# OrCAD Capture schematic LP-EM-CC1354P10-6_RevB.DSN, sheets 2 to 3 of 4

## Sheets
2 2_Peripherals: size A3
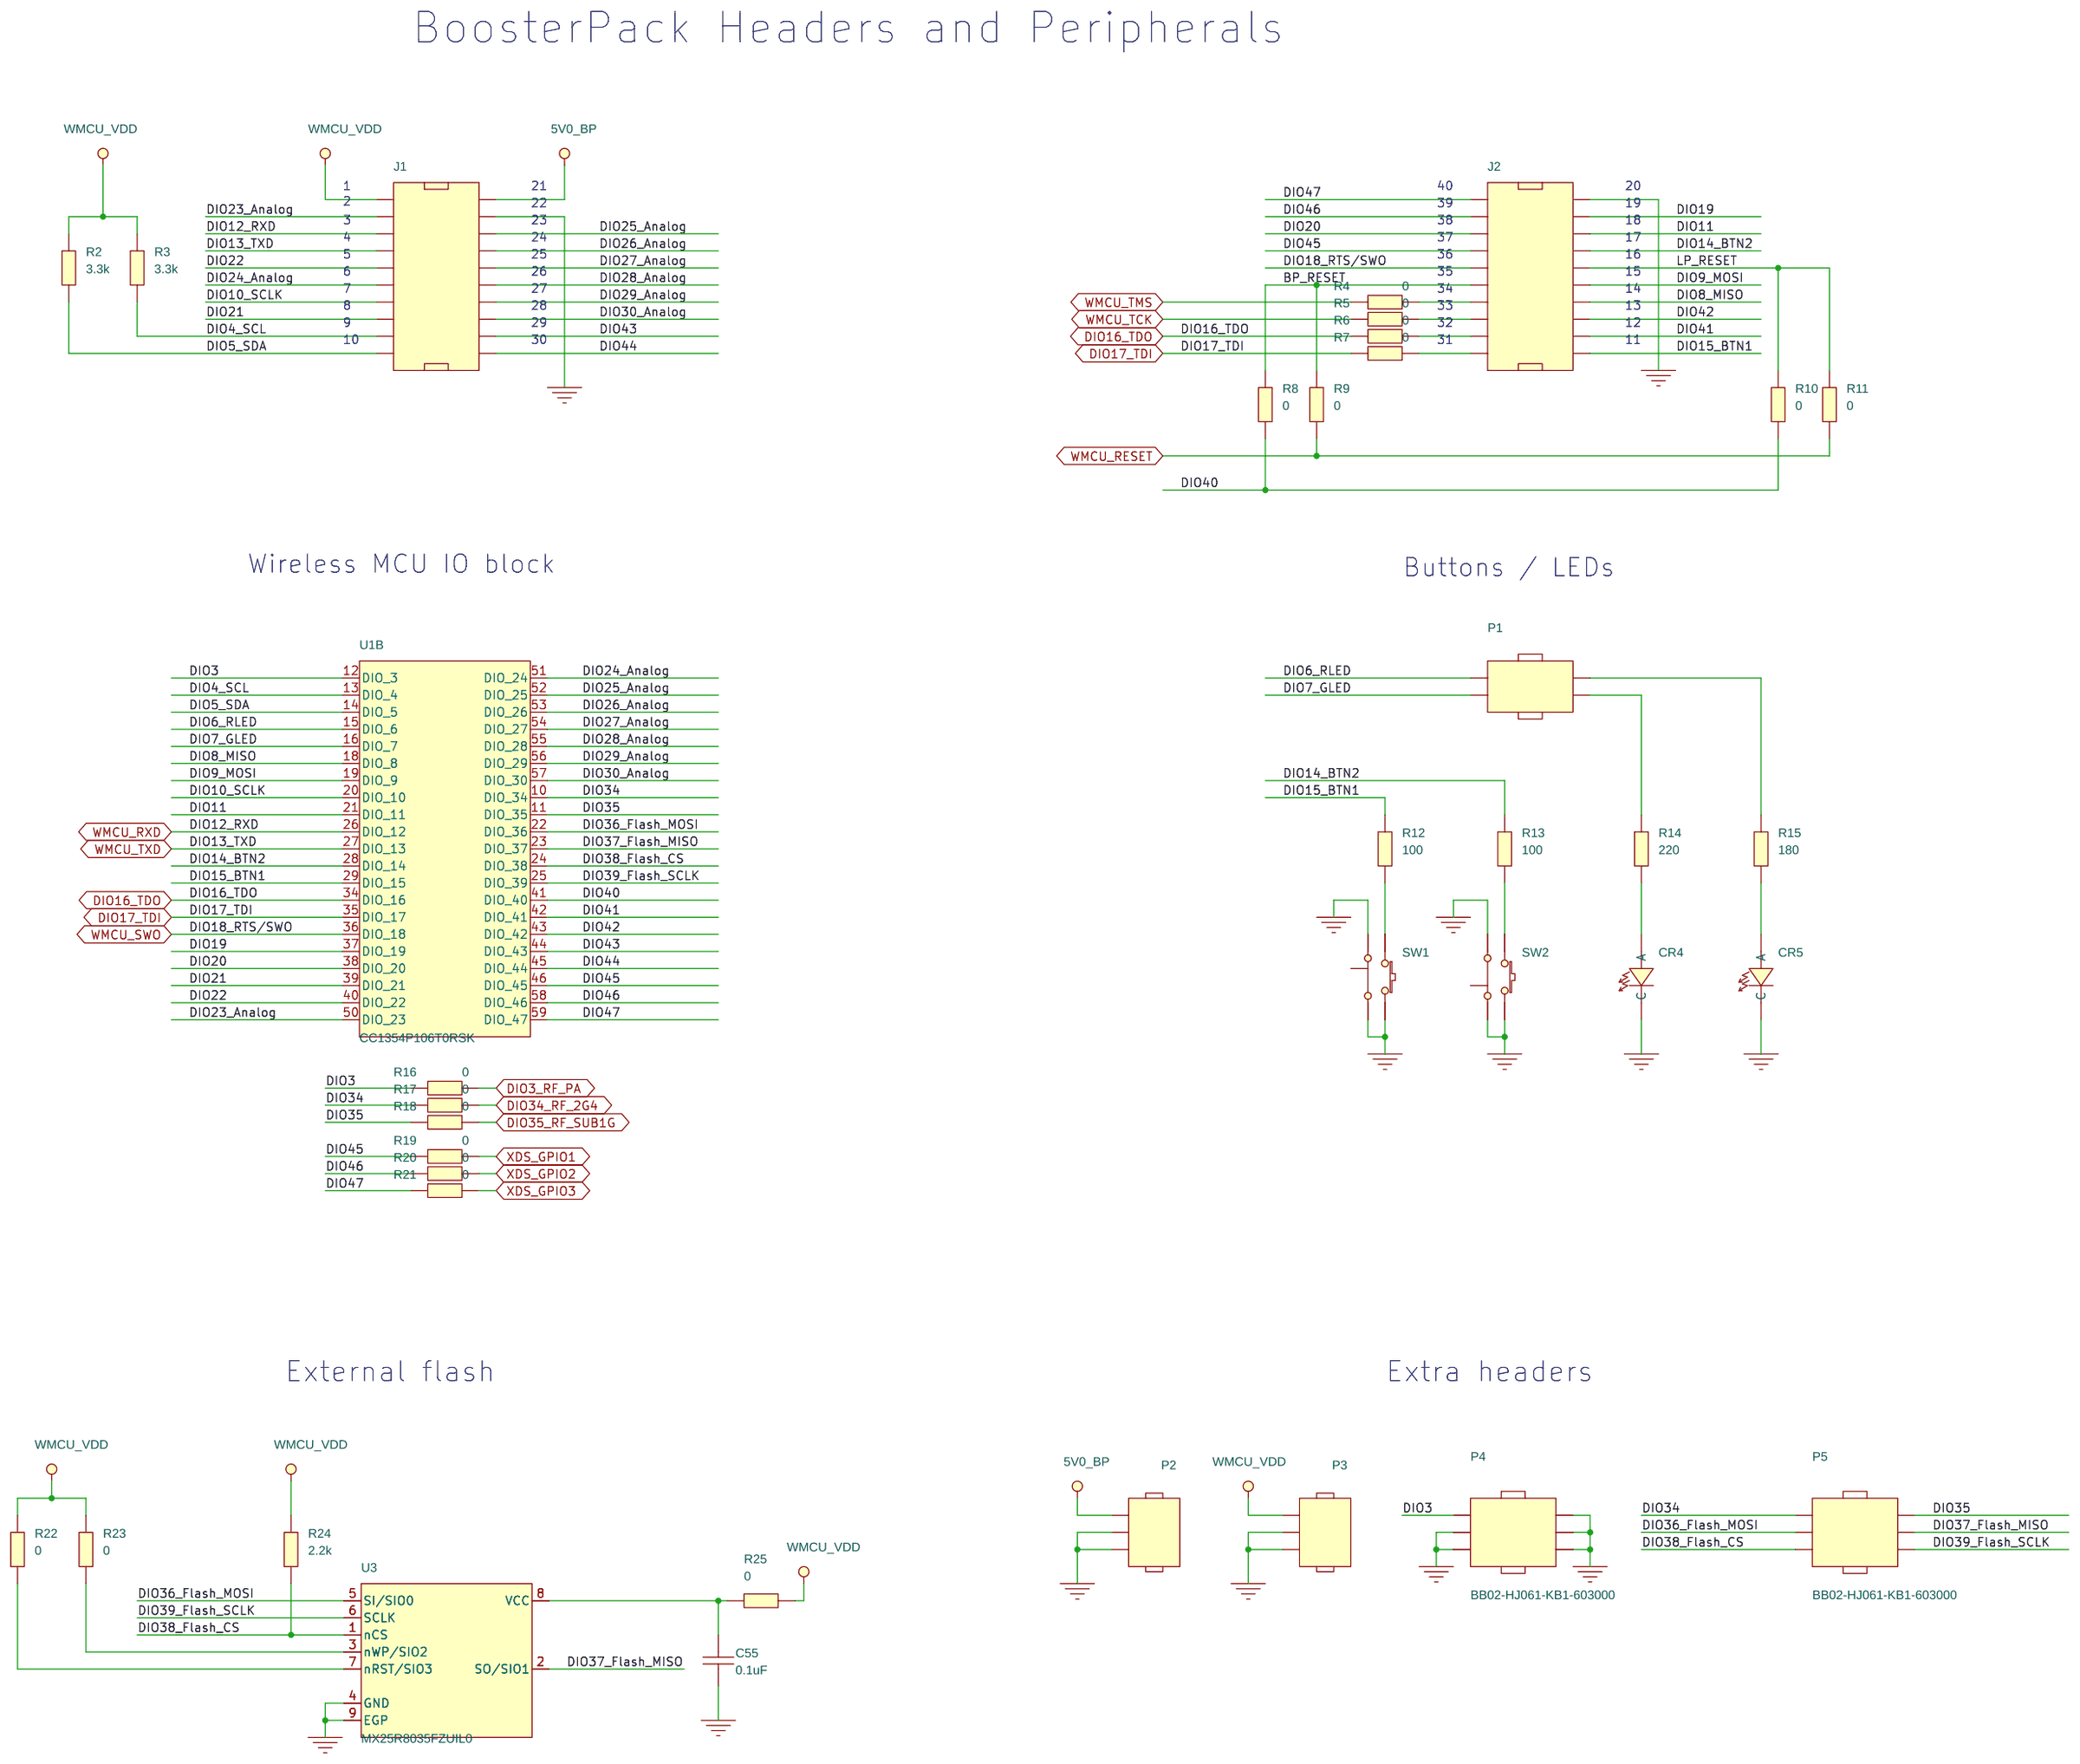
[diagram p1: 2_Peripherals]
3 3_Debugger Interface: size A3
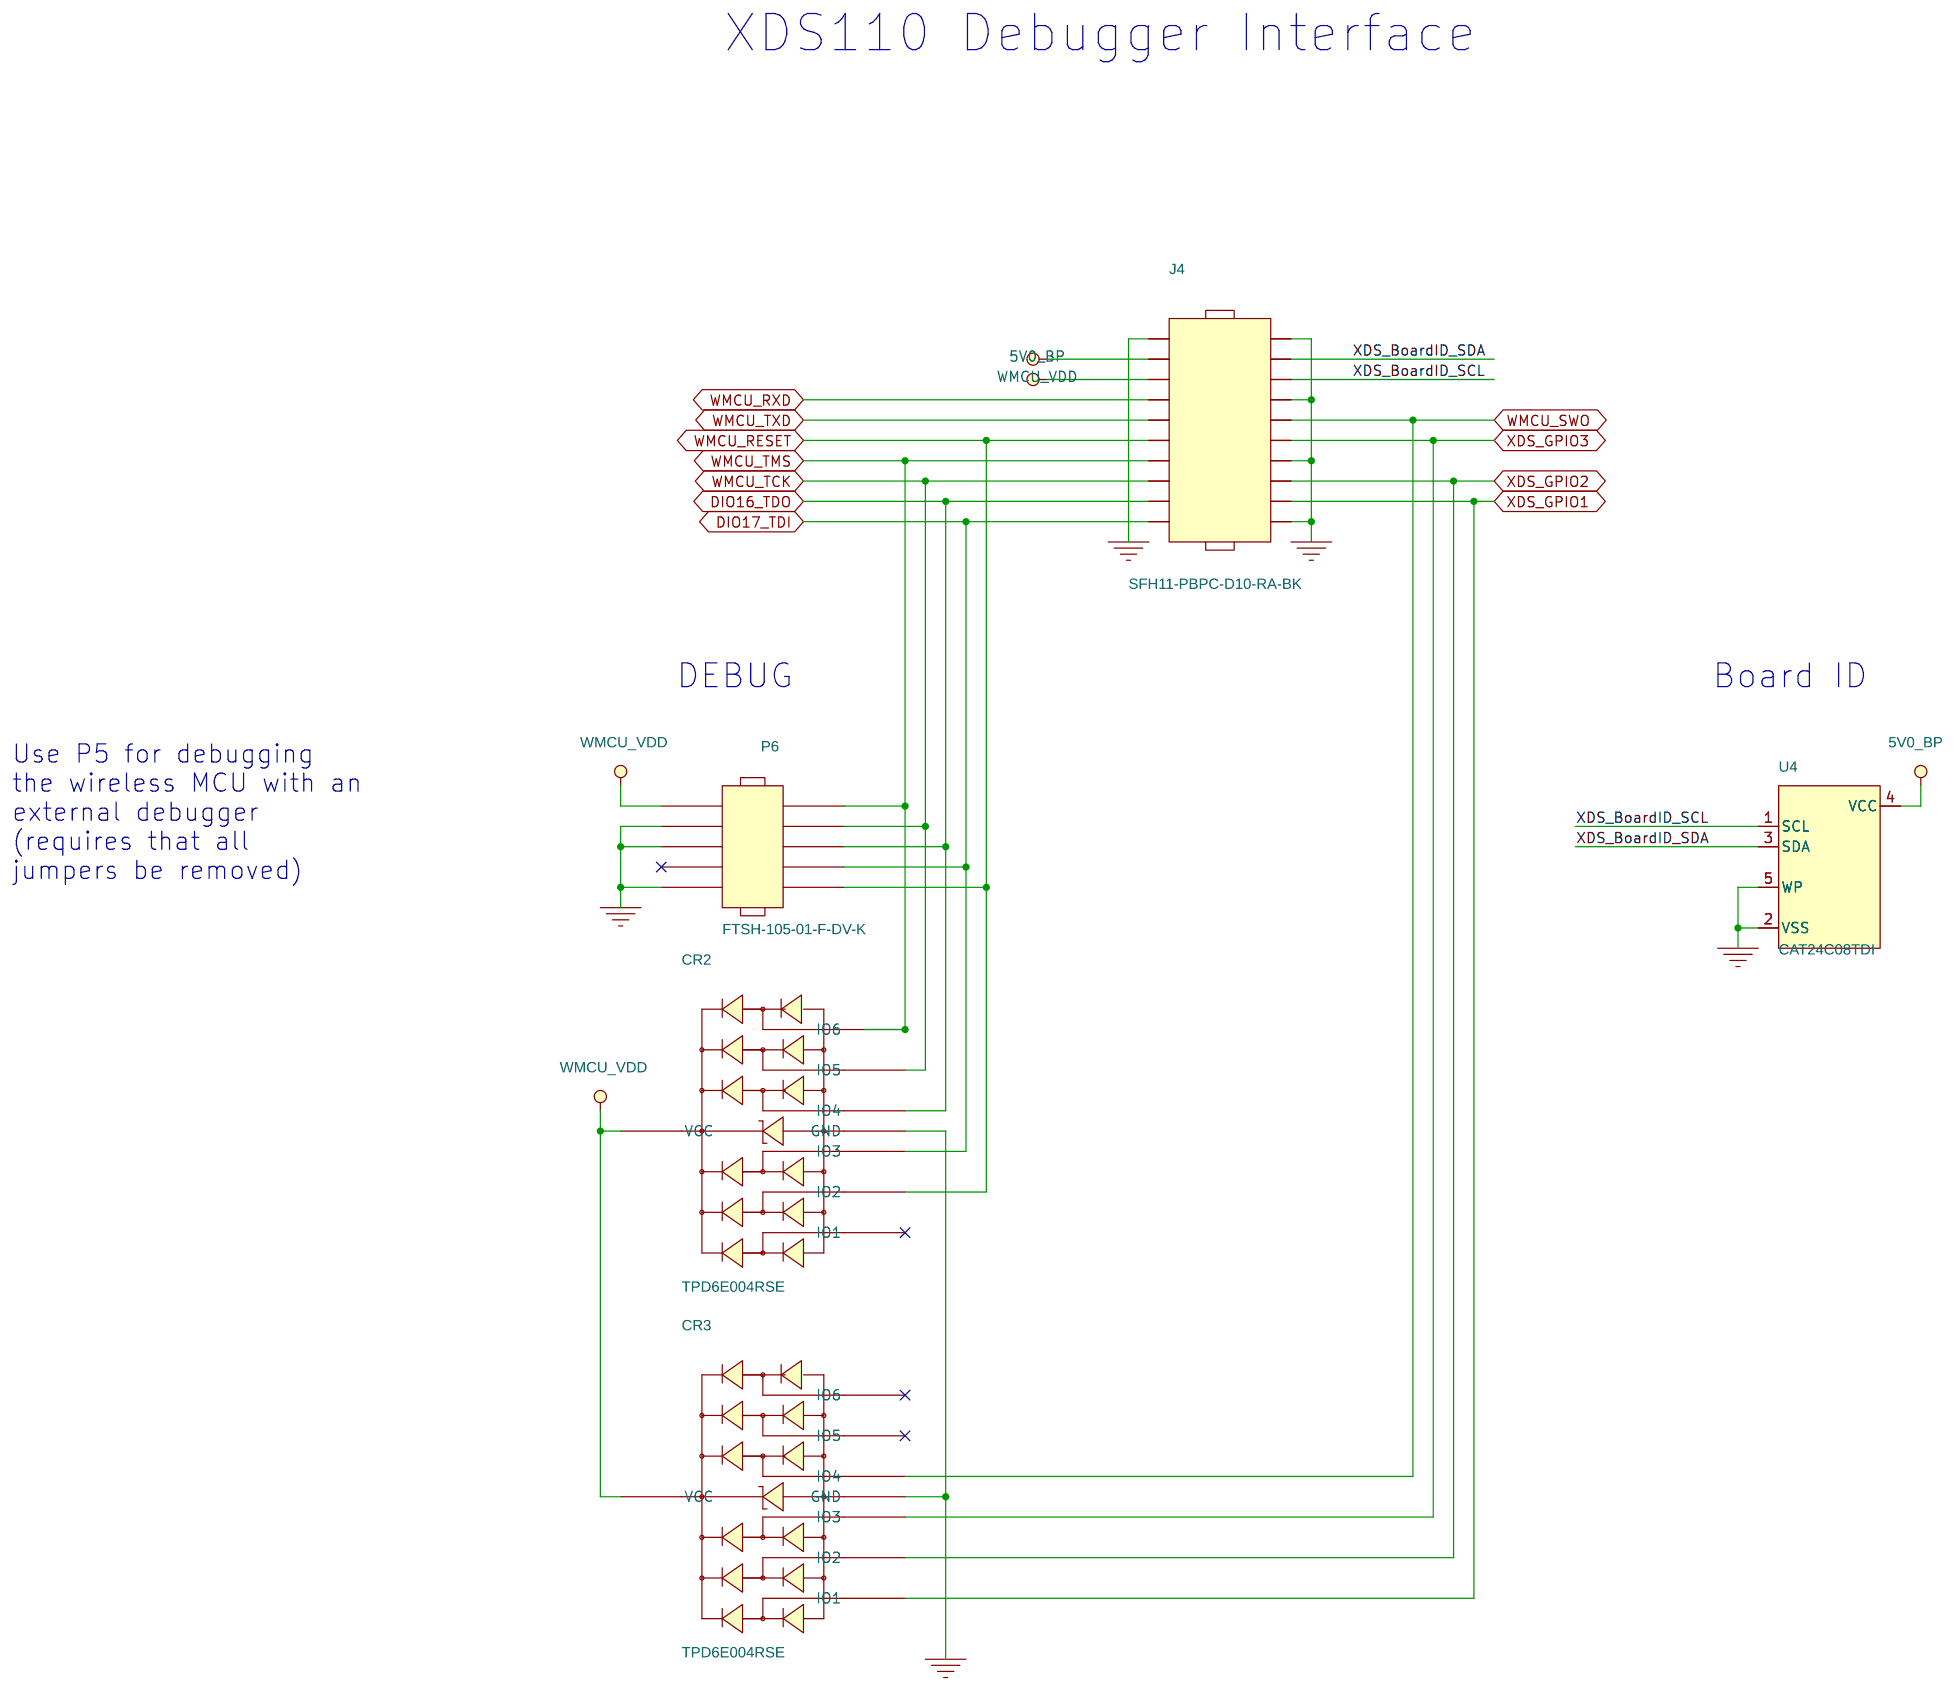
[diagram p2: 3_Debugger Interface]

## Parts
sheet 1_RF
U1  CC1354P106T0RSK  [QFNFC40P800X800X100-65A2N]  (sections A,B)
sheet 2_Peripherals
C55  0.1uF  [CAPC0603X35B2N]
CR4  LPL296-J2L2-25  [LEDC1707X65N]
CR5  LS L296-P2Q2-1  [LEDC1708X67N]
J1  SSQ-110-23-L-D  [SAMTEC_SSQ11023LD_A2B]
J2  SSQ-110-23-L-D  [SAMTEC_SSQ11023LD_A2B]
P1  BB02-HJ041-KB1-603000  [GRADCONN_BB02HJ041KB1603000_A2B]
P2  BB02-HC031-KB1-603000  [GRADCONN_BB02HC031KB1603000_A2B]
P3  BB02-HC031-KB1-603000  [GRADCONN_BB02HC031KB1603000_A2B]
P4  BB02-HJ061-KB1-603000  [GRADCONN_BB02HJ061KB1603000_A2B]
P5  BB02-HJ061-KB1-603000  [GRADCONN_BB02HJ061KB1603000_A2B]
R2  3.3k  [RESC1005X40B2N]
R3  3.3k  [RESC1005X40B2N]
R4  0  [RESC1608X55A2N]
R5  0  [RESC1608X55A2N]
R6  0  [RESC1608X55A2N]
R7  0  [RESC1608X55A2N]
R8  0  [RESC1608X55A2N]
R9  0  [RESC1608X55A2N]
R10  0  [RESC1608X55A2N]
R11  0  [RESC1608X55A2N]
R12  100  [RESC1005X40B2N]
R13  100  [RESC1005X40B2N]
R14  220  [RESC1005X40B2N]
R15  180  [RESC1005X40B2N]
R16  0  [RESC0603X35B2N]
R17  0  [RESC0603X35B2N]
R18  0  [RESC0603X35B2N]
R19  0  [RESC0603X35B2N]
R20  0  [RESC0603X35B2N]
R21  0  [RESC0603X35B2N]
R22  0  [RESC1608X55A2N]
R23  0  [RESC1608X55A2N]
R24  2.2k  [RESC1005X40B2N]
R25  0  [RESC1608X55A2N]
SW1  1188E-1K2  [SW_1188E1K2V_A2N]
SW2  1188E-1K2  [SW_1188E1K2V_A2N]
U3  MX25R8035FZUIL0  [SON50P300X200X60-9B2N]
sheet 3_Debugger Interface
CR2  TPD6E004RSE  [QFNFC50P150X150X60-8A2N]
CR3  TPD6E004RSE  [QFNFC50P150X150X60-8A2N]
J4  SFH11-PBPC-D10-RA-BK  [SULLINS_SFH11PBPCD10RABK_A2B]
P6  FTSH-105-01-F-DV-K  [SAMTEC_FTSH10501FDVK_A2N]
U4  CAT24C08TDI  [SOT95P280X100-5A2N]

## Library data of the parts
U1 = IC_RF_CC1354P106T0RSK_VQFN64: IC, CUSTOM, TEXAS INSTRUMENTS, CC1354P106T0RSK, VQFN64-EP, SMD; ALT_SYMBOLS: QFNFC40P800X800X100-65A2L,QFNFC40P800X800X100-65A2M; Additional Datasheet URL: https://www.ti.com/; Country of Origin: Missing Info; Datasheet URL: N/A; Mass: N/A; Maximum Operating Temperature: N/A; Minimum Operating Temperature: N/A; Mounting Type: SMD; NOTEfied URL: https://notefied-dynamic-precision.com/NOTEfiedWebInterface/part/show?partNumber=18-36708; Notes: Custom component.; PCB Package: VQFN64-EP; Packing Size: N/A; Packing Type: Missing Info; Part Number: 18-36708; Part Type: IC|CUSTOM; REACH/SVHC Details: SVHC List Version; ROHS: Missing Info; Revision: R015; Status: Released; Texas Part Status: Under Review; Type: IC; Vendor: TEXAS INSTRUMENTS; Vendor Part Status: Preliminary
C55 = CAPACITOR: CAPACITOR, CERAMIC X7S, 0.1uF, 10V, -10%/+10%, -55DEGC/+125DEGC, 0201, SMD; ALT_SYMBOLS: CAPC0603X35B2L,CAPC0603X35B2M; Additional Datasheet URL: https://www.murata.com/en-us/products/productdetail?partno=GRM033C71A104KE14%23; AutoDoc File: https://notefied-dynamic-precision.com/DB/Apps/Desktop/Item/Object.aspx?id=115293; BU Name: TEXAS INSTRUMENTS NORWAY; Budgetary Price: 0.01328 USD; Client Status: UNDER_REVIEW; Country of Origin: China,Japan,Philippines,Singapore; Datasheet URL: https://search.murata.co.jp/Ceramy/image/img/A01X/G101/ENG/GRM033C71A104KE14-01A.pdf; Datasheet URL 1: http://psearch.en.murata.com/capacitor/product/GRM155R71E104KE14%23.pdf; Datasheet URL 2: http://search.murata.co.jp/Ceramy/image/img/w_hinm/L0005E.pdf; Definied Quality: INDUSTRIAL; Dielectric Type: X7S; Esd Level: N/A; Lead Time: 23; LifeCycle Status: ACTIVE; MPN: CAPACITOR_0402_100nF_X7R_M_+/-10%_10V; MPN Status: ACTIVE; MSL: N/A; MTBF: N/A; MTBF Standard: N/A; Manufacturer: MANUFACTURER SELECTION; Mass: 0.00033g; Max Oper Temp: +125DEGC; Max Tol: +10%; Maximum Operating Temperature: +125DEGC; Maximum Tolerance: +10%; Min Oper Temp: -55DEGC; Min Tol: -10%; Minimum Operating Temperature: -55DEGC; Minimum Tolerance: -10%; Mounting Type: SMD; NOTE Status: PREFERRED; NOTEfied URL: https://notefied-dynamic-precision.com/NOTEfiedWebInterface/part/show?partNumber=02-10308; Old Footprint: CAPC1005X60N; PCB Package: 0201; Packing Size: 15000; Packing Type: Tape & Reel; Part Number: 02-10308; Part Type: Capacitor|CERAMIC|0201|STANDARD; REACH/SVHC Compliance: Compliant; REACH/SVHC Details: SVHC List Version Jan 23, 2024 (240); REACH/SVHC Source: REACH Declaration; REACH/SVHC Status: Unaffected; REACH/SVHC_COMPLIANCE: COMPLIANT; REACH/SVHC_DETAILS: SVHC LIST VERSION Jun 20, 2016; REACH/SVHC_SOURCE: REACH DECLARATION; REACH/SVHC_STATUS: UNAFFECTED; ROHS: Compliant; Rated Voltage: 10V; Revision: R018; RoHS Status: ROHS_COMPLIANT; Rtd Voltage: 25V; Status: Released; Texas Part Status: Under Review; Type: Capacitor; Vendor: MURATA; Vendor Part Number: GRM033C71A104KE14D; Vendor Part Status: Active; WEIGHT: 0.0016g
CR4 = LED: OPTO, LED, InGaAlP, GREEN, 560nm, 1.8V TO 2.4V, 0.02A, 0603, SMD; ALT_SYMBOLS: LEDC1707X65L,LEDC1707X65M; Additional Datasheet URL: https://ams-osram.com/products/leds/color-leds/osram-smartled-0603-lp-l296; AutoDoc File: http://notefied-dynamic-precision.com/DB/Apps/Desktop/Item/Object.aspx?id=81622; Budget Currency: USD; Budget Price: 0.1263; CLASS: IC; Country of Origin: Missing Info; Datasheet URL: https://look.ams-osram.com/m/37da308c02be71bd/original/LP-L296.pdf; Datasheet URL 1: N/A; Datasheet URL 2: http://catalog.osram-os.com/jsp/download.jsp?rootPath=/media/&name=LP_L296.pdf&docPath=Graphics/00077128_0.pdf&url=/media//_en/Graphics/00077128_0.pdf; Definied Quality: INDUSTRIAL; Esd Level: HBM 2kV; FPLIST: LEDC1707X65N,LEDC1707X65L,LEDC1707X65M; MPN: LP L296-J2L2-25; MPN Status: NRND; MSL: 2; MTBF: N/A; MTBF Standard: N/A; Manufacturer: OSRAM; Mass: 0.0016g; Max Oper Temp: +100DEGC; Maximum Operating Temperature: +100DEGC; Min Oper Temp: -40DEGC; Minimum Operating Temperature: -40DEGC; Mounting Type: SMD; NOTE Status: NOT_PREFERRED; NOTEfied URL: https://notefied-dynamic-precision.com/NOTEfiedWebInterface/part/show?partNumber=15-01023; PCB Package: 0603; Packing Size: 5000; Packing Type: Tape & Reel; Part Number: 15-01023; Part Type: Opto|LED|0603; REACH/SVHC Compliance: Compliant; REACH/SVHC Details: SVHC List Version Jan 12, 2017 (173); REACH/SVHC Source: REACH Declaration; REACH/SVHC Status: Unaffected; ROHS: Compliant; Rated Current: 0.02A; Rated Voltage: 1.8V TO 2.4V; Revision: R049; RoHS Status: ROHS_COMPLIANT; Rtd Current: 0.02A; Rtd Power: 0.08W; Rtd Voltage: 2V; Status: Released; Type: Opto; Vendor: OSRAM; Vendor Part Number: LP L296-J2L2-25; Vendor Part Status: Active; WEIGHT: 0.002g
CR5 = LED: OPTO, LED, RED, 630nm, 1.8V TO 2.3V, 0.02A, 0603, SMD; ALT_SYMBOLS: LEDC1708X67L,LEDC1708X67M; Additional Datasheet URL: https://ams-osram.com/products/leds/color-leds/osram-smartled-0603-ls-l296; AutoDoc File: http://notefied-dynamic-precision.com/DB/Apps/Desktop/Item/Object.aspx?id=88355; Budget Currency: USD; Budget Price: 0.089; CLASS: IC; Country of Origin: Missing Info; Datasheet URL: https://look.ams-osram.com/m/1ce9402ea49508df/original/LS-L296.pdf; Datasheet URL 1: http://www.osram-os.com/osram_os/en/products/product-catalog/led-light-emitting-diodes/smartled-0603/ls-l296/index.jsp?search_result=%2fosram_os%2fen%2fsearch%2fadvanced_search.jsp%3faction%3ddosearch%26inp_searchterm_1%3dLS%2bL296-P2Q2-1%26website_name%3; Datasheet URL 2: http://www.osram-os.com/Graphics/XPic5/00077119_0.pdf/LS%20L296%20-%20SMARTLED%200603.pdf; Definied Quality: INDUSTRIAL; Esd Level: HBM 2kV; FPLIST: LEDC1708X67N,LEDC1708X67L,LEDC1708X67M; MPN Status: NRND; MSL: 2; MTBF: N/A; MTBF Standard: N/A; Manufacturer: OSRAM; Mass: 0.0016g; Max Oper Temp: +100DEGC; Maximum Operating Temperature: +100DEGC; Min Oper Temp: -40DEGC; Minimum Operating Temperature: -40DEGC; Mounting Type: SMD; NOTE Status: PREFERRED; NOTEfied URL: https://notefied-dynamic-precision.com/NOTEfiedWebInterface/part/show?partNumber=15-01169; PCB Package: 0603; PPCB Recomendation: Inactive for new design [Alert:0001]; Packing Size: 5000; Packing Type: Tape & Reel; Part Number: 15-01169; Part Type: Opto|LED|0603; REACH/SVHC Compliance: Compliant; REACH/SVHC Details: SVHC List Version Jan 12, 2017 (173); REACH/SVHC Source: REACH Declaration; REACH/SVHC Status: Unaffected; ROHS: Compliant; Rated Current: 0.02A; Rated Voltage: 1.8V TO 2.3V; Revision: R050; RoHS Status: ROHS_COMPLIANT; Rtd Current: 0.06A; Rtd Voltage: 1.8V TO 2.3V; Status: Released; Type: Opto; Vendor: OSRAM; Vendor Part Status: Active; WEIGHT: 0.002g
J1 J2 = CONN_HEADER_2X10_J_S_V1: CONNECTOR, HEADER, FEMALE, STRAIGHT, 2 ROW(S), 20 PIN(S), 2.54mm, PTH; ALT_SYMBOLS: SAMTEC_SSQ11023LD_A2C,SAMTEC_SSQ11023LD_A2A; Additional Datasheet URL: https://www.samtec.com/products/ssq-110-23-l-d; AutoDoc File: http://notefied-dynamic-precision.com/DB/Apps/Desktop/Item/Object.aspx?id=104387; Budget Currency: USD; Budget Price: 2.14; Budgetary Price: 2.62146 USD; Country of Origin: China,Costa Rica,Malaysia,Singapore,Taiwan,United States,Vietnam; Datasheet URL: https://suddendocs.samtec.com/catalog_english/ssq_th.pdf; Datasheet URL 1: http://suddendocs.samtec.com/prints/ssq-1xx-xx-xxx-x-xx-xxx-xx-x-mkt.pdf; Datasheet URL 2: http://suddendocs.samtec.com/catalog_english/ssq_th.pdf; Definied Quality: INDUSTRIAL; Esd Level: N/A; FPLIST: SAMTEC_SSQ11023LD_A2B,SAMTEC_SSQ11023LD_A2C,SAMTEC_SSQ11023LD_A2A; Lead Time: 12; LifeCycle Status: ACTIVE; MPN Status: ACTIVE; MSL: N/A; Manufacturer: SAMTEC; Mass: 2.45594g; Max Oper Temp: +125DEGC; Maximum Operating Temperature: +125DEGC; Min Oper Temp: -55DEGC; Minimum Operating Temperature: -55DEGC; Mounting Type: PTH; NOTE Status: PREFERRED; NOTEfied URL: https://notefied-dynamic-precision.com/NOTEfiedWebInterface/part/show?partNumber=06-04997; No Of Pos: 20; No Of Rows: 2; Number of Positions: 20; Number of Rows: 2; Packing Size: 21; Packing Type: Bulk; Part Number: 06-04997; Part Type: Connector|HEADER|STANDARD; Pitch: 2.54mm; REACH/SVHC Compliance: Compliant; REACH/SVHC Details: SVHC List Version Jan 12, 2017 (173); REACH/SVHC Source: REACH Declaration & Material Declaration; REACH/SVHC Status: Unaffected; ROHS: Compliant; Rated Current: 6.3A; Rated Voltage: 465VAC / 655VDC; Revision: R034; RoHS Status: ROHS_COMPLIANT; Rtd Current: 6.3A; Status: Released; Texas Part Status: Under Review; Type: Connector; Vendor: SAMTEC; Vendor Part Status: Active; WEIGHT: 2.45594g
P1 = CONN_HEADER_2X2_P: CONNECTOR, HEADER, MALE, STRAIGHT, 2 ROWS, 4 PINS, PITCH 2.54mm, PTH; ALT_SYMBOLS: GRADCONN_BB02HJ041KB1603000_A2C,GRADCONN_BB02HJ041KB1603000_A2A; Additional Datasheet URL: https://www.gradconn.com/Files/Drawings/BB02-HJ.pdf; AutoDoc File: http://notefied-dynamic-precision.com/DB/Apps/Desktop/Item/Object.aspx?id=104391; Country of Origin: Missing Info; Datasheet URL: https://www.gradconn.com/Files/Specs/BTB-2.54mm-Header-specification.pdf; Datasheet URL 1: http://www.gradconn.com/Files/Drawings/BB02-HJ.pdf; Datasheet URL 2: http://www.gradconn.com/Files/Specs/BTB-2.54mm-Header-specification.pdf; FPLIST: GRADCONN_BB02HJ041KB1603000_A2B,GRADCONN_BB02HJ041KB1603000_A2C,GRADCONN_BB02HJ041KB1603000_A2A; MPN Status: ACTIVE; Manufacturer: GRADCONN; Mass: N/A; Max Oper Temp: +105DEGC; Maximum Operating Temperature: +105DEGC; Min Oper Temp: -40DEGC; Minimum Operating Temperature: -40DEGC; Mounting Type: PTH; NOTE Status: PREFERRED; NOTEfied URL: https://notefied-dynamic-precision.com/NOTEfiedWebInterface/part/show?partNumber=06-04999; No Of Pos: 4; No Of Rows: 2; Number of Positions: 4; Number of Rows: 2; Packing Size: N/A; Packing Type: Missing Info; Part Number: 06-04999; Part Type: Connector|HEADER|STANDARD; Pitch: 2.54mm; REACH/SVHC Compliance: Compliant; REACH/SVHC Details: SVHC List Version Jun 20, 2016; REACH/SVHC Source: RoHS & REACH Declaration; REACH/SVHC Status: Unaffected; ROHS: Compliant; Rated Current: 3A; Revision: R021; RoHS Status: ROHS_COMPLIANT; Rtd Current: 3A; Status: Released; Texas Part Status: Under Review; Type: Connector; Vendor: GRADCONN; Vendor Part Status: Active
P2 P3 = CONN_HEADER_3_P_S: CONNECTOR, HEADER, MALE, STRAIGHT, 1 ROW, 3 PINS, PITCH 2.54mm, PTH; ALT_SYMBOLS: GRADCONN_BB02HC031KB1603000_A2C,GRADCONN_BB02HC031KB1603000_A2A; Additional Datasheet URL: https://www.gradconn.com/Files/Drawings/BB02-HC.pdf; AutoDoc File: http://notefied-dynamic-precision.com/DB/Apps/Desktop/Item/Object.aspx?id=104636; Country of Origin: Missing Info; Datasheet URL: https://www.gradconn.com/Files/Specs/BTB-2.54mm-Header-specification.pdf; Datasheet URL 1: http://www.gradconn.com/Files/Drawings/BB02-HC.pdf; Datasheet URL 2: http://www.gradconn.com/Files/Specs/BTB-2.54mm-Header-specification.pdf; FPLIST: GRADCONN_BB02HC031KB1603000_A2B,GRADCONN_BB02HC031KB1603000_A2C,GRADCONN_BB02HC031KB1603000_A2A; MPN Status: ACTIVE; Manufacturer: GRADCONN; Mass: N/A; Max Oper Temp: +105DEGC; Maximum Operating Temperature: +105DEGC; Min Oper Temp: -40DEGC; Minimum Operating Temperature: -40DEGC; Mounting Type: PTH; NOTE Status: PREFERRED; NOTEfied URL: https://notefied-dynamic-precision.com/NOTEfiedWebInterface/part/show?partNumber=06-05038; No Of Pos: 3; No Of Rows: 1; Number of Positions: 3; Number of Rows: 1; Packing Size: N/A; Packing Type: Missing Info; Part Number: 06-05038; Part Type: Connector|HEADER|STANDARD; Pitch: 2.54mm; REACH/SVHC Compliance: Compliant; REACH/SVHC Details: SVHC List Version Jun 20, 2016; REACH/SVHC Source: RoHS & REACH Declaration; REACH/SVHC Status: Unaffected; ROHS: Compliant; Rated Current: 3A; Rated Voltage: 250V; Revision: R021; RoHS Status: ROHS_COMPLIANT; Rtd Current: 3A; Rtd Voltage: 250V; Status: Released; Texas Part Status: Under Review; Type: Connector; Vendor: GRADCONN; Vendor Part Status: Active
P4 P5 = CONN_HEADER_2X3_P_V2: CONNECTOR, HEADER, MALE, STRAIGHT, 2 ROWS, 6 PINS, PITCH 2.54mm, PTH; ALT_SYMBOLS: GRADCONN_BB02HJ061KB1603000_A2A,GRADCONN_BB02HJ061KB1603000_A2C; Additional Datasheet URL: https://www.gradconn.com/files/Drawings/BB02-HJ.pdf; Datasheet URL: https://www.gradconn.com/Files/Specs/BTB-2.54mm-Header-specification.pdf; Maximum Operating Temperature: +105DEGC; Minimum Operating Temperature: -40DEGC; Mounting Type: PTH; NOTEfied URL: https://notefied-dynamic-precision.com/NOTEfiedWebInterface/part/show?partNumber=06-10909; Number of Positions: 6; Number of Rows: 2; Packing Size: N/A; Packing Type: Loose; Part Number: 06-10909; Part Type: Connector|HEADER|STANDARD; Pitch: 2.54mm; REACH/SVHC Compliance: Compliant; REACH/SVHC Details: SVHC List Version Jun 25, 2020; REACH/SVHC Source: RoHS & REACH Declaration; REACH/SVHC Status: Unaffected; ROHS: Compliant; Rated Current: 3A; Revision: R001; Status: Released; Texas Part Status: Under Review; Type: Connector; Vendor: GRADCONN; Vendor Part Status: Active
R2 R3 = RESISTOR: RESISTOR, THICK FILM, 3.3k, -5%/+5%, 0.063W, 50V, -55DEGC/+155DEGC, 0402, SMD; Additional Datasheet URL: N/A; AutoDoc File: https://notefied-dynamic-precision.com/DB/Apps/Desktop/Item/Object.aspx?id=114561; BU Name: TEXAS INSTRUMENTS NORWAY; Budget Currency: EUR; Budget Price: 0.014; Budgetary Price: 0.014 EUR; Client Status: UNDER_REVIEW; Country of Origin: Israel; Datasheet URL: https://www.vishay.com/docs/20035/dcrcwe3.pdf; Datasheet URL 1: http://www.vishay.com/docs/20035/dcrcwe3.pdf; Datasheet URL 2: N/A; Definied Quality: INDUSTRIAL; Esd Level: N/A; Exclusive for Customers: TEXAS INSTRUMENTS NORWAY; Lead Time: 18; LifeCycle Status: ACTIVE; MPN: RESISTOR_0402_3.3k_+/-5%_50V_0.063W_M_+/-200ppm; MPN Status: ACTIVE; MSL: N/A; MTBF: N/A; MTBF Standard: N/A; Manufacturer: MANUFACTURER SELECTION; Mass: 0.00065g; Max Oper Temp: +155DEGC; Max TC: +200PPM/DEGC; Max Tol: +5%; Maximum Operating Temperature: +155DEGC; Maximum Temperature Coefficient: +200PPM/DEGC; Maximum Tolerance: +5%; Min Oper Temp: -55DEGC; Min TC: -200PPM/DEGC; Min Tol: -5%; Minimum Operating Temperature: -55DEGC; Minimum Temperature Coeficient: -200PPM/DEGC; Minimum Tolerance: -5%; Mounting Type: SMD; NOTE Status: PREFERRED; NOTEfied URL: https://notefied-dynamic-precision.com/NOTEfiedWebInterface/part/show?partNumber=01-22488; Notes: Standard item: Duplicate Reason: custom footprint for TEXAS INSTRUMENTS NORWAY.; Old Footprint: RESC1005X40N; PCB Package: 0402; Packing Size: 10000; Packing Type: Tape & Reel; Part Number: 01-22488; Part Type: Resistor|0402|STANDARD; REACH/SVHC Compliance: Compliant; REACH/SVHC Details: SVHC List Version Jun 20, 2016; REACH/SVHC Source: Material Declaration; REACH/SVHC Status: Unaffected; REACH/SVHC_COMPLIANCE: COMPLIANT; REACH/SVHC_DETAILS: SVHC LIST VERSION Jun 20, 2016; REACH/SVHC_SOURCE: MATERIAL DECLARATION; REACH/SVHC_STATUS: UNAFFECTED; ROHS: Exempt; Rated Current: N/A; Rated Power: 0.063W; Rated Voltage: 50V; Resistor Type: THICK FILM; Revision: R021; RoHS Status: ROHS_COMPLIANT; Rtd Current: N/A; Rtd Power: 0.063W; Rtd Voltage: 50V; Status: Released; Texas Part Status: Under Review; Type: Resistor; Vendor: VISHAY; Vendor Part Number: CRCW04023K30JNED; Vendor Part Status: Active; WEIGHT: 0.00065g
R4 R5 = RESISTOR: RESISTOR, THICK FILM, 0, 0R/+0.02R, 0.1W, 2A, -55DEGC/+155DEGC, 0603, SMD; ALT_SYMBOLS: RESC1608X55A2L,RESC1608X55A2M; Additional Datasheet URL: N/A; AutoDoc File: http://notefied-dynamic-precision.com/DB/Apps/Desktop/Item/Object.aspx?id=48377; Budget Currency: N/A; Budget Price: N/A; Budgetary Price: 0.005 EUR; Country of Origin: Israel; Datasheet URL: http://www.vishay.com/docs/20035/dcrcwe3.pdf; Datasheet URL 1: N/A; Datasheet URL 2: N/A; Esd Level: N/A; Lead Time: 29; LifeCycle Status: ACTIVE; MPN: DNM; MPN Status: ACTIVE; MSL: N/A; MTBF: N/A; MTBF Standard: N/A; Manufacturer: DO NOT MOUNT; Mass: 0.002g; Max Oper Temp: N/A; Max TC: N/A; Max Tol: N/A; Maximum Operating Temperature: +155DEGC; Maximum Temperature Coefficient: N/A; Maximum Tolerance: +0.02R; Min Oper Temp: N/A; Min TC: N/A; Min Tol: N/A; Minimum Operating Temperature: -55DEGC; Minimum Temperature Coeficient: N/A; Minimum Tolerance: 0R; Mounting Type: SMD; NOTE Status: PREFERRED; NOTEfied URL: https://notefied-dynamic-precision.com/NOTEfiedWebInterface/part/show?partNumber=01-20043; Old Footprint: RESC1608X55N,0603; PCB Package: 0603; Packing Size: 20000; Packing Type: Tape & Reel; Part Number: 01-20043; Part Type: Resistor|0603|JUMPER; REACH/SVHC Compliance: Compliant; REACH/SVHC Details: SVHC List Version Jun 15, 2015; REACH/SVHC Source: Material Declaration; REACH/SVHC Status: Unaffected; ROHS: Exempt; Rated Current: 2A; Rated Power: 0.1W; Rated Voltage: N/A; Resistor Type: THICK FILM; Revision: R010; RoHS Status: MISSING_INFO; Rtd Current: N/A; Rtd Power: N/A; Rtd Voltage: N/A; Status: Released; Type: Resistor; Vendor: VISHAY; Vendor Part Number: CRCW06030000Z0EC; Vendor Part Status: Active; WEIGHT: N/A
R6-R8 R11 R25 = RESISTOR: RESISTOR, THICK FILM, JUMPER, 0, 0R/+0.02R, 0.1W, 2A, -55DEGC/+155DEGC, 0603, SMD; ALT_SYMBOLS: RESC1608X55A2L,RESC1608X55A2M; Additional Datasheet URL: N/A; AutoDoc File: https://notefied-dynamic-precision.com/DB/Apps/Desktop/Item/Object.aspx?id=94847; BU Name: DYNAMIC PRECISION GDANSK; Budget Currency: USD; Budget Price: 0.0016; Budgetary Price: 0.005 EUR; Client Status: UNDER_REVIEW; Country of Origin: Israel; Datasheet URL: http://www.vishay.com/docs/20035/dcrcwe3.pdf; Datasheet URL 1: http://www.vishay.com/docs/20035/dcrcwe3.pdf; Datasheet URL 2: N/A; Esd Level: N/A; Lead Time: 29; LifeCycle Status: ACTIVE; MPN: DNM; MPN Status: ACTIVE; MSL: N/A; MTBF: N/A; MTBF Standard: N/A; Manufacturer: DO NOT MOUNT; Mass: 0.002g; Max Oper Temp: +155DEGC; Max TC: N/A; Max Tol: +0.02R; Maximum Operating Temperature: +155DEGC; Maximum Temperature Coefficient: N/A; Maximum Tolerance: +0.02R; Min Oper Temp: -55DEGC; Min TC: N/A; Min Tol: 0R; Minimum Operating Temperature: -55DEGC; Minimum Temperature Coeficient: N/A; Minimum Tolerance: 0R; Mounting Type: SMD; NOTE Status: PREFERRED; NOTEfied URL: https://notefied-dynamic-precision.com/NOTEfiedWebInterface/part/show?partNumber=01-20043; Old Footprint: RESC1608X55N,0603; PCB Package: 0603; Packing Size: 20000; Packing Type: Tape & Reel; Part Number: 01-20043; Part Type: Resistor|0603|JUMPER; REACH/SVHC Compliance: Compliant; REACH/SVHC Details: SVHC List Version Jan 23, 2024 (240); REACH/SVHC Source: REACH Declaration & Material Declaration; REACH/SVHC Status: Unaffected; REACH/SVHC_COMPLIANCE: COMPLIANT; REACH/SVHC_DETAILS: SVHC LIST VERSION Jun 15, 2015; REACH/SVHC_SOURCE: MATERIAL DECLARATION; REACH/SVHC_STATUS: UNAFFECTED; ROHS: Exempt; Rated Current: 2A; Rated Power: 0.1W; Rated Voltage: N/A; Resistor Type: THICK FILM; Revision: R013; RoHS Status: ROHS_COMPLIANT_WITH_EXEMPTION; Rtd Current: N/A; Rtd Power: 0.1W; Rtd Voltage: 75V; Status: Released; Type: Resistor; Vendor: VISHAY; Vendor Part Number: CRCW06030000Z0EC; Vendor Part Status: Active; WEIGHT: 0.002g
R9 R10 = RESISTOR: RESISTOR, THICK FILM, 0, 0R/+0.02R, 0.1W, 2A, -55DEGC/+155DEGC, 0603, SMD; ALT_SYMBOLS: RESC1608X55A2L,RESC1608X55A2M; Additional Datasheet URL: N/A; AutoDoc File: https://notefied-dynamic-precision.com/DB/Apps/Desktop/Item/Object.aspx?id=94847; BU Name: DYNAMIC PRECISION GDANSK; Budget Currency: USD; Budget Price: 0.0016; Budgetary Price: 0.005 EUR; Client Status: UNDER_REVIEW; Country of Origin: Israel; Datasheet URL: http://www.vishay.com/docs/20035/dcrcwe3.pdf; Datasheet URL 1: http://www.vishay.com/docs/20035/dcrcwe3.pdf; Datasheet URL 2: N/A; Esd Level: N/A; Lead Time: 29; LifeCycle Status: ACTIVE; MPN: DNM; MPN Status: ACTIVE; MSL: N/A; MTBF: N/A; MTBF Standard: N/A; Manufacturer: DO NOT MOUNT; Mass: 0.002g; Max Oper Temp: +155DEGC; Max TC: N/A; Max Tol: +0.02R; Maximum Operating Temperature: +155DEGC; Maximum Temperature Coefficient: N/A; Maximum Tolerance: +0.02R; Min Oper Temp: -55DEGC; Min TC: N/A; Min Tol: 0R; Minimum Operating Temperature: -55DEGC; Minimum Temperature Coeficient: N/A; Minimum Tolerance: 0R; Mounting Type: SMD; NOTE Status: PREFERRED; NOTEfied URL: https://notefied-dynamic-precision.com/NOTEfiedWebInterface/part/show?partNumber=01-20043; Old Footprint: RESC1608X55N,0603; PCB Package: 0603; Packing Size: 20000; Packing Type: Tape & Reel; Part Number: 01-20043; Part Type: Resistor|0603|JUMPER; REACH/SVHC Compliance: Compliant; REACH/SVHC Details: SVHC List Version Jun 15, 2015; REACH/SVHC Source: Material Declaration; REACH/SVHC Status: Unaffected; REACH/SVHC_COMPLIANCE: COMPLIANT; REACH/SVHC_DETAILS: SVHC LIST VERSION Jun 15, 2015; REACH/SVHC_SOURCE: MATERIAL DECLARATION; REACH/SVHC_STATUS: UNAFFECTED; ROHS: Exempt; Rated Current: 2A; Rated Power: 0.1W; Rated Voltage: N/A; Resistor Type: THICK FILM; Revision: R010; RoHS Status: ROHS_COMPLIANT_WITH_EXEMPTION; Rtd Current: N/A; Rtd Power: 0.1W; Rtd Voltage: 75V; Status: Released; Type: Resistor; Vendor: VISHAY; Vendor Part Number: CRCW06030000Z0EC; Vendor Part Status: Active; WEIGHT: 0.002g
R12 R13 = RESISTOR: RESISTOR, THICK FILM, 100, -5%/+5%, 0.063W, 50V, -55DEGC/+155DEGC, 0402, SMD; Additional Datasheet URL: https://www.vishay.com/en/product/20035/; AutoDoc File: https://notefied-dynamic-precision.com/DB/Apps/Desktop/Item/Object.aspx?id=114555; BU Name: TEXAS INSTRUMENTS NORWAY; Budget Currency: USD; Budget Price: 0.0014; Budgetary Price: 0.0014 USD; Client Status: UNDER_REVIEW; Country of Origin: China,Israel; Datasheet URL: https://www.vishay.com/docs/20035/dcrcwe3.pdf; Datasheet URL 1: http://www.vishay.com/docs/20035/dcrcwe3.pdf; Datasheet URL 2: N/A; Definied Quality: INDUSTRIAL; Esd Level: N/A; Lead Time: 16; LifeCycle Status: ACTIVE; MPN: RESISTOR_0402_100_+/-5%_50V_0.063W_M_+/-200ppm; MPN Status: ACTIVE; MSL: N/A; MTBF: N/A; MTBF Standard: N/A; Manufacturer: MANUFACTURER SELECTION; Mass: 0.00065g; Max Oper Temp: +155DEGC; Max TC: +200PPM/DEGC; Max Tol: +5%; Maximum Operating Temperature: +155DEGC; Maximum Temperature Coefficient: +200PPM/DEGC; Maximum Tolerance: +5%; Min Oper Temp: -55DEGC; Min TC: -200PPM/DEGC; Min Tol: -5%; Minimum Operating Temperature: -55DEGC; Minimum Temperature Coeficient: -200PPM/DEGC; Minimum Tolerance: -5%; Mounting Type: SMD; NOTE Status: PREFERRED; NOTEfied URL: https://notefied-dynamic-precision.com/NOTEfiedWebInterface/part/show?partNumber=01-22482; Notes: Standard item: Duplicate Reason: custom footprint for TEXAS INSTRUMENTS NORWAY.; Old Footprint: RESC1005X40N; PCB Package: 0402; Packing Size: 10000; Packing Type: Tape & Reel; Part Number: 01-22482; Part Type: Resistor|0402|STANDARD; REACH/SVHC Compliance: Compliant; REACH/SVHC Details: SVHC List Version Jan 23, 2024 (240); REACH/SVHC Source: REACH Declaration & Material Declaration; REACH/SVHC Status: Unaffected; REACH/SVHC_COMPLIANCE: COMPLIANT; REACH/SVHC_DETAILS: SVHC LIST VERSION Jun 20, 2016; REACH/SVHC_SOURCE: MATERIAL DECLARATION; REACH/SVHC_STATUS: UNAFFECTED; ROHS: Exempt; Rated Current: N/A; Rated Power: 0.063W; Rated Voltage: 50V; Resistor Type: THICK FILM; Revision: R043; RoHS Status: ROHS_COMPLIANT; Rtd Current: N/A; Rtd Power: 0.063W; Rtd Voltage: 50V; Status: Released; Texas Part Status: Under Review; Type: Resistor; Vendor: VISHAY; Vendor Part Number: CRCW0402100RJNED; Vendor Part Status: Active; WEIGHT: 0.00065g
R14 = RESISTOR: RESISTOR, THICK FILM, 220, -5%/+5%, 0.063W, 50V, -55DEGC/+155DEGC, 0402, SMD; Additional Datasheet URL: https://www.vishay.com/en/product/20035/; AutoDoc File: https://notefied-dynamic-precision.com/DB/Apps/Desktop/Item/Object.aspx?id=113319; BU Name: TEXAS INSTRUMENTS NORWAY; Budget Currency: EUR; Budget Price: 0.014; Budgetary Price: 0.014 EUR; Client Status: UNDER_REVIEW; Country of Origin: China,Israel; Datasheet URL: https://www.vishay.com/docs/20035/dcrcwe3.pdf; Datasheet URL 1: http://www.vishay.com/docs/20035/dcrcwe3.pdf; Datasheet URL 2: N/A; Definied Quality: INDUSTRIAL; Esd Level: N/A; Lead Time: 18; LifeCycle Status: ACTIVE; MPN: RESISTOR_0402_220_+/-5%_50V_0.063W_M_+/-200ppm; MPN Status: ACTIVE; MSL: N/A; MTBF: N/A; MTBF Standard: N/A; Manufacturer: MANUFACTURER SELECTION; Mass: 0.00065g; Max Oper Temp: +155DEGC; Max TC: +200PPM/DEGC; Max Tol: +5%; Maximum Operating Temperature: +155DEGC; Maximum Temperature Coefficient: +200PPM/DEGC; Maximum Tolerance: +5%; Min Oper Temp: -55DEGC; Min TC: -200PPM/DEGC; Min Tol: -5%; Minimum Operating Temperature: -55DEGC; Minimum Temperature Coeficient: -200PPM/DEGC; Minimum Tolerance: -5%; Mounting Type: SMD; NOTE Status: PREFERRED; NOTEfied URL: https://notefied-dynamic-precision.com/NOTEfiedWebInterface/part/show?partNumber=01-22346; Notes: Standard item: Duplicate Reason: custom footprint for TEXAS INSTRUMENTS NORWAY.; Old Footprint: RESC1005X40N; PCB Package: 0402; Packing Size: 10000; Packing Type: Tape & Reel; Part Number: 01-22346; Part Type: Resistor|0402|STANDARD; REACH/SVHC Compliance: Compliant; REACH/SVHC Details: SVHC List Version Jan 23, 2024 (240); REACH/SVHC Source: REACH Declaration & Material Declaration; REACH/SVHC Status: Unaffected; REACH/SVHC_COMPLIANCE: COMPLIANT; REACH/SVHC_DETAILS: SVHC LIST VERSION Jun 20, 2016; REACH/SVHC_SOURCE: MATERIAL DECLARATION; REACH/SVHC_STATUS: UNAFFECTED; ROHS: Exempt; Rated Current: N/A; Rated Power: 0.063W; Rated Voltage: 50V; Resistor Type: THICK FILM; Revision: R040; RoHS Status: ROHS_COMPLIANT_WITH_EXEMPTION; Rtd Current: N/A; Rtd Power: 0.063W; Rtd Voltage: 50V; Status: Released; Texas Part Status: Under Review; Type: Resistor; Vendor: VISHAY; Vendor Part Number: CRCW0402220RJNED; Vendor Part Status: Active; WEIGHT: 0.00065g
R15 = RESISTOR: RESISTOR, THICK FILM, 180, -5%/+5%, 0.063W, 50V, -55DEGC/+155DEGC, 0402, SMD; Additional Datasheet URL: https://www.vishay.com/en/product/20035/; AutoDoc File: https://notefied-dynamic-precision.com/DB/Apps/Desktop/Item/Object.aspx?id=113318; BU Name: TEXAS INSTRUMENTS NORWAY; Budget Currency: EUR; Budget Price: 0.014; Budgetary Price: 0.014 EUR; Client Status: UNDER_REVIEW; Country of Origin: China,Israel; Datasheet URL: https://www.vishay.com/docs/20035/dcrcwe3.pdf; Datasheet URL 1: http://www.vishay.com/docs/20035/dcrcwe3.pdf; Datasheet URL 2: N/A; Definied Quality: INDUSTRIAL; Esd Level: N/A; Lead Time: 18; LifeCycle Status: ACTIVE; MPN: RESISTOR_0402_180_+/-5%_50V_0.063W_M_+/-200ppm; MPN Status: ACTIVE; MSL: N/A; MTBF: N/A; MTBF Standard: N/A; Manufacturer: MANUFACTURER SELECTION; Mass: 0.00065g; Max Oper Temp: +155DEGC; Max TC: +200PPM/DEGC; Max Tol: +5%; Maximum Operating Temperature: +155DEGC; Maximum Temperature Coefficient: +200PPM/DEGC; Maximum Tolerance: +5%; Min Oper Temp: -55DEGC; Min TC: -200PPM/DEGC; Min Tol: -5%; Minimum Operating Temperature: -55DEGC; Minimum Temperature Coeficient: -200PPM/DEGC; Minimum Tolerance: -5%; Mounting Type: SMD; NOTE Status: PREFERRED; NOTEfied URL: https://notefied-dynamic-precision.com/NOTEfiedWebInterface/part/show?partNumber=01-22345; Notes: Standard item: Duplicate Reason: custom footprint for TEXAS INSTRUMENTS NORWAY.; Old Footprint: RESC1005X40N; PCB Package: 0402; Packing Size: 10000; Packing Type: Tape & Reel; Part Number: 01-22345; Part Type: Resistor|0402|STANDARD; REACH/SVHC Compliance: Compliant; REACH/SVHC Details: SVHC List Version Jan 23, 2024 (240); REACH/SVHC Source: REACH Declaration & Material Declaration; REACH/SVHC Status: Unaffected; REACH/SVHC_COMPLIANCE: COMPLIANT; REACH/SVHC_DETAILS: SVHC LIST VERSION Jun 20, 2016; REACH/SVHC_SOURCE: MATERIAL DECLARATION; REACH/SVHC_STATUS: UNAFFECTED; ROHS: Exempt; Rated Current: N/A; Rated Power: 0.063W; Rated Voltage: 50V; Resistor Type: THICK FILM; Revision: R040; RoHS Status: ROHS_COMPLIANT_WITH_EXEMPTION; Rtd Current: N/A; Rtd Power: 0.063W; Rtd Voltage: 50V; Status: Released; Texas Part Status: Under Review; Type: Resistor; Vendor: VISHAY; Vendor Part Number: CRCW0402180RJNED; Vendor Part Status: Active; WEIGHT: 0.00065g
R16-R18 = RESISTOR: RESISTOR, THICK FILM, JUMPER, 0, 0R/+0.05R, 0.05W, 1A, -55DEGC/+155DEGC, 0201, SMD; ALT_SYMBOLS: RESC0603X35B2L,RESC0603X35B2M; Additional Datasheet URL: https://www.vishay.com/en/product/20052/; Budgetary Price: 0.00605 EUR; Country of Origin: China,Israel,Taiwan; Datasheet URL: https://www.vishay.com/docs/20052/crcw0201e3.pdf; Lead Time: 20; Mass: 0.000143039g; Maximum Operating Temperature: +155DEGC; Maximum Temperature Coefficient: N/A; Maximum Tolerance: +0.05R; Minimum Operating Temperature: -55DEGC; Minimum Temperature Coeficient: N/A; Minimum Tolerance: 0R; Mounting Type: SMD; NOTEfied URL: https://notefied-dynamic-precision.com/NOTEfiedWebInterface/part/show?partNumber=01-04043; PCB Package: 0201; Packing Size: 10000; Packing Type: Tape & Reel; Part Number: 01-04043; Part Type: Resistor|0201|JUMPER; REACH/SVHC Compliance: Compliant; REACH/SVHC Details: SVHC List Version Jan 23, 2024 (240); REACH/SVHC Source: REACH Declaration & Material Declaration; REACH/SVHC Status: Unaffected; ROHS: Exempt; Rated Current: 1A; Rated Power: 0.05W; Rated Voltage: N/A; Resistor Type: THICK FILM; Revision: R053; Status: Released; Texas Part Number: TEXAS_00014; Texas Part Status: Under Review; Type: Resistor; Vendor: VISHAY; Vendor Part Number: CRCW02010000Z0ED; Vendor Part Status: Active
R19-R21 = RESISTOR: RESISTOR, THICK FILM, 0, 0R/+0.05R, 0.05W, 1A, -55DEGC/+155DEGC, 0201, SMD; ALT_SYMBOLS: RESC0603X35B2L,RESC0603X35B2M; Additional Datasheet URL: N/A; Budgetary Price: 0.006 EUR; Country of Origin: Israel,Taiwan; Datasheet URL: https://www.vishay.com/docs/20052/crcw0201e3.pdf; Lead Time: 20; Mass: 0.000143039g; Maximum Operating Temperature: +155DEGC; Maximum Temperature Coefficient: N/A; Maximum Tolerance: +0.05R; Minimum Operating Temperature: -55DEGC; Minimum Temperature Coeficient: N/A; Minimum Tolerance: 0R; Mounting Type: SMD; NOTEfied URL: https://notefied-dynamic-precision.com/NOTEfiedWebInterface/part/show?partNumber=01-04043; PCB Package: 0201; Packing Size: 10000; Packing Type: Tape & Reel; Part Number: 01-04043; Part Type: Resistor|0201|JUMPER; REACH/SVHC Compliance: Compliant; REACH/SVHC Details: SVHC List Version Dec 17, 2015; REACH/SVHC Source: Material Declaration; REACH/SVHC Status: Unaffected; ROHS: Exempt; Rated Current: 1A; Rated Power: 0.05W; Rated Voltage: N/A; Resistor Type: THICK FILM; Revision: R038; Status: Released; Type: Resistor; Vendor: VISHAY; Vendor Part Number: CRCW02010000Z0ED; Vendor Part Status: Active
R22 R23 = RESISTOR: RESISTOR, THICK FILM, 0, 0R/+0.02R, 0.1W, 2A, -55DEGC/+155DEGC, 0603, SMD; ALT_SYMBOLS: RESC1608X55A2L,RESC1608X55A2M; Additional Datasheet URL: N/A; AutoDoc File: https://notefied-dynamic-precision.com/DB/Apps/Desktop/Item/Object.aspx?id=113312; BU Name: TEXAS INSTRUMENTS NORWAY; Budget Currency: N/A; Budget Price: N/A; Budgetary Price: 0.005 EUR; Country of Origin: Israel; Datasheet URL: http://www.vishay.com/docs/20035/dcrcwe3.pdf; Datasheet URL 1: N/A; Datasheet URL 2: N/A; Esd Level: N/A; Lead Time: 29; LifeCycle Status: ACTIVE; MPN: DNM; MPN Status: ACTIVE; MSL: N/A; MTBF: N/A; MTBF Standard: N/A; Manufacturer: DO NOT MOUNT; Mass: 0.002g; Max Oper Temp: N/A; Max TC: N/A; Max Tol: N/A; Maximum Operating Temperature: +155DEGC; Maximum Temperature Coefficient: N/A; Maximum Tolerance: +0.02R; Min Oper Temp: N/A; Min TC: N/A; Min Tol: N/A; Minimum Operating Temperature: -55DEGC; Minimum Temperature Coeficient: N/A; Minimum Tolerance: 0R; Mounting Type: SMD; NOTE Status: PREFERRED; NOTEfied URL: https://notefied-dynamic-precision.com/NOTEfiedWebInterface/part/show?partNumber=01-20043; Old Footprint: RESC1005X40N,0402; PCB Package: 0603; Packing Size: 20000; Packing Type: Tape & Reel; Part Number: 01-20043; Part Type: Resistor|0603|JUMPER; REACH/SVHC Compliance: Compliant; REACH/SVHC Details: SVHC List Version Jun 15, 2015; REACH/SVHC Source: Material Declaration; REACH/SVHC Status: Unaffected; ROHS: Exempt; Rated Current: 2A; Rated Power: 0.1W; Rated Voltage: N/A; Resistor Type: THICK FILM; Revision: R010; RoHS Status: MISSING_INFO; Rtd Current: N/A; Rtd Power: N/A; Rtd Voltage: N/A; Status: Released; Type: Resistor; Vendor: VISHAY; Vendor Part Number: CRCW06030000Z0EC; Vendor Part Status: Active; WEIGHT: N/A
R24 = RESISTOR: RESISTOR, THICK FILM, 2.2k, -5%/+5%, 0.063W, 50V, -55DEGC/+155DEGC, 0402, SMD; Additional Datasheet URL: https://www.vishay.com/en/product/20035/; AutoDoc File: https://notefied-dynamic-precision.com/DB/Apps/Desktop/Item/Object.aspx?id=114560; BU Name: TEXAS INSTRUMENTS NORWAY; Budget Currency: EUR; Budget Price: 0.014; Budgetary Price: 0.014 EUR; Client Status: UNDER_REVIEW; Country of Origin: China,Israel; Datasheet URL: https://www.vishay.com/docs/20035/dcrcwe3.pdf; Datasheet URL 1: http://www.vishay.com/docs/20035/dcrcwe3.pdf; Datasheet URL 2: N/A; Definied Quality: INDUSTRIAL; Esd Level: N/A; Lead Time: 18; LifeCycle Status: ACTIVE; MPN: RESISTOR_0402_2.2k_+/-5%_50V_0.063W_M_+/-200ppm; MPN Status: ACTIVE; MSL: N/A; MTBF: N/A; MTBF Standard: N/A; Manufacturer: MANUFACTURER SELECTION; Mass: 0.00065g; Max Oper Temp: +155DEGC; Max TC: +200PPM/DEGC; Max Tol: +5%; Maximum Operating Temperature: +155DEGC; Maximum Temperature Coefficient: +200PPM/DEGC; Maximum Tolerance: +5%; Min Oper Temp: -55DEGC; Min TC: -200PPM/DEGC; Min Tol: -5%; Minimum Operating Temperature: -55DEGC; Minimum Temperature Coeficient: -200PPM/DEGC; Minimum Tolerance: -5%; Mounting Type: SMD; NOTE Status: PREFERRED; NOTEfied URL: https://notefied-dynamic-precision.com/NOTEfiedWebInterface/part/show?partNumber=01-22487; Notes: Standard item: Duplicate Reason: custom footprint for TEXAS INSTRUMENTS NORWAY.; Old Footprint: RESC1005X40N; PCB Package: 0402; Packing Size: 10000; Packing Type: Tape & Reel; Part Number: 01-22487; Part Type: Resistor|0402|STANDARD; REACH/SVHC Compliance: Compliant; REACH/SVHC Details: SVHC List Version Jan 23, 2024 (240); REACH/SVHC Source: REACH Declaration & Material Declaration; REACH/SVHC Status: Unaffected; REACH/SVHC_COMPLIANCE: COMPLIANT; REACH/SVHC_DETAILS: SVHC LIST VERSION Jun 20, 2016; REACH/SVHC_SOURCE: MATERIAL DECLARATION; REACH/SVHC_STATUS: UNAFFECTED; ROHS: Exempt; Rated Current: N/A; Rated Power: 0.063W; Rated Voltage: 50V; Resistor Type: THICK FILM; Revision: R040; RoHS Status: ROHS_COMPLIANT; Rtd Current: N/A; Rtd Power: 0.063W; Rtd Voltage: 50V; Status: Released; Texas Part Status: Under Review; Type: Resistor; Vendor: VISHAY; Vendor Part Number: CRCW04022K20JNED; Vendor Part Status: Active; WEIGHT: 0.00065g
SW1 SW2 = SWITCH_TACT_V2: SWITCH, TACTILE, 0.05A@12VDC, 0.05A@250VAC, SMD; ALT_SYMBOLS: SW_1188E1K2V_A2L,SW_1188E1K2V_A2M; Additional Datasheet URL: http://www.dip.com.tw/en/en-product-information/en-switch004/item/2445-1188; AutoDoc File: http://notefied-dynamic-precision.com/DB/Apps/Desktop/Item/Object.aspx?id=104642; Budgetary Price: 0.474 EUR; CLASS: IC; Country of Origin: China; Datasheet URL: http://www.dip.com.tw/en/en-product-information/en-switch004/item/download/2483_bfc264bcfe9982a2b01570916dd931c3; Datasheet URL 1: N/A; Datasheet URL 2: http://www.dip.com.tw/en/en-product-information/en-switch004; FPLIST: SW_1188E1K2V_A2N,SW_1188E1K2V_A2L,SW_1188E1K2V_A2M; Lead Time: 18; MPN: 1188E-1K2-V-TR; MPN Status: ACTIVE; Manufacturer: DIPTRONICS; Mass: N/A; Max Oper Temp: +70DEGC; Maximum Operating Temperature: +70DEGC; Min Oper Temp: -25DEGC; Minimum Operating Temperature: -25DEGC; Mounting Type: SMD; NOTE Status: PREFERRED; NOTEfied URL: https://notefied-dynamic-precision.com/NOTEfiedWebInterface/part/show?partNumber=08-00293; Packing Size: 1500; Packing Type: Tape & Reel; Part Number: 08-00293; Part Type: Switch|TACTILE; REACH/SVHC Compliance: Compliant; REACH/SVHC Details: SVHC List Version Dec 17, 2015 (168); REACH/SVHC Source: REACH Declaration; REACH/SVHC Status: Unaffected; ROHS: Compliant; Rated Current: 0.05A; Rated Voltage: 12VDC; Revision: R037; RoHS Status: ROHS_COMPLIANT; Rtd Current: 0.05A; Rtd Voltage: 12V; Status: Released; Texas Part Status: Under Review; Type: Switch; Vendor: DIPTRONICS; Vendor Part Number: 1188E-1K2-V-TR; Vendor Part Status: Active
U3 = IC_FLASH_MX25R8035F_USON8: IC, MEMORY, FLASH, OTHER, 8Mbit, 8M X 1bit / 4M X 2bit / 2M X 4bit, 12ns, 1.65V TO 3.6V, uSON8, SMD; ALT_SYMBOLS: SON50P300X200X60-9B2L,SON50P300X200X60-9B2M; Additional Datasheet URL: https://www.macronix.com/en-us/products/NOR-Flash/Serial-NOR-Flash/Pages/spec.aspx?p=MX25R8035F&m=Serial%20NOR%20Flash&n=PM2164; AutoDoc File: http://notefied-dynamic-precision.com/DB/Apps/Desktop/Item/Object.aspx?id=104624; Budgetary Price: 0.42218 USD; Country of Origin: Taiwan; Datasheet URL: https://www.macronix.com/Lists/Datasheet/Attachments/8749/MX25R8035F,%20Wide%20Range,%208Mb,%20v1.6.pdf; Datasheet URL 1: N/A; Datasheet URL 2: http://www.macronix.com/Lists/DataSheet/Attachments/2570/MX25R8035F,%20Wide%20Range,%208Mb,%20v0.04.pdf; FPLIST: SON50P300X200X60-9B2N,SON50P300X200X60-9B2L,SON50P300X200X60-9B2M; Lead Time: 10; MPN Status: ACTIVE; Manufacturer: MACRONIX; Mass: N/A; Max Oper Temp: +85DEGC; Maximum Operating Temperature: +85DEGC; Min Oper Temp: -40DEGC; Minimum Operating Temperature: -40DEGC; Mounting Type: SMD; NOTE Status: PREFERRED; NOTEfied URL: https://notefied-dynamic-precision.com/NOTEfiedWebInterface/part/show?partNumber=18-31726; PCB Package: uSON8; Packing Size: 100; Packing Type: Tube; Part Number: 18-31726; Part Type: IC|MEMORY|FLASH|OTHER; REACH/SVHC Compliance: Compliant; REACH/SVHC Details: SVHC List Version Jun 14, 2023 (235); REACH/SVHC Source: RoHS & REACH Declaration; REACH/SVHC Status: Unaffected; ROHS: Compliant; Rated Voltage: 1.65V TO 3.6V; Revision: R038; RoHS Status: ROHS_COMPLIANT; Rtd Voltage: 1.65V TO 3.6V; Status: Released; Texas Part Status: Under Review; Type: IC; Vendor: MACRONIX; Vendor Part Status: Active
CR2 CR3 = DIODE_TVS_TPD6E004_QFN8_V1: DIODE, PROTECTION, ESD ARRAY - 6 CHANNELS, 0.9V TO 5.5V, VBR:7V, -40DEGC/+85DEGC, QFN8, SMD; ALT_SYMBOLS: QFNFC50P150X150X60-8A2L,QFNFC50P150X150X60-8A2M; Additional Datasheet URL: https://www.ti.com/product/TPD6E004/part-details/TPD6E004RSER; AutoDoc File: https://notefied-dynamic-precision.com/DB/Apps/Desktop/Item/Object.aspx?id=74721; BU Name: DYNAMIC PRECISION GDANSK; Budget Currency: USD; Budget Price: 0.27; Budgetary Price: 0.295 USD; CLASS: IC; Client Status: UNDER_REVIEW; Country of Origin: China,Thailand; Datasheet URL: https://www.ti.com/lit/ds/symlink/tpd6e004.pdf; Datasheet URL 1: http://www.ti.com/lit/ds/symlink/tpd6e004.pdf; Datasheet URL 2: http://www.ti.com/litv/pdf/mpqf207b; FPLIST: QFN50P150X150X60-8N,QFN50P150X150X60-8AN; Lead Time: 10; Mass: 0.0033g; Max Oper Temp: +85DEGC; Maximum Operating Temperature: +85DEGC; Min Oper Temp: -40DEGC; Minimum Operating Temperature: -40DEGC; Mounting Type: SMD; NOTEfied URL: https://notefied-dynamic-precision.com/NOTEfiedWebInterface/part/show?partNumber=14-05493; PCB Package: QFN8; Packing Size: 3000; Packing Type: Tape & Reel; Part Number: 14-05493; Part Type: Diode|PROTECTION; REACH/SVHC Compliance: Compliant; REACH/SVHC Details: SVHC List Version Jun 20, 2016 (169); REACH/SVHC Source: Material Declaration; REACH/SVHC Status: Unaffected; ROHS: Compliant; Rated Power: N/A; Rated Voltage: 7V; Revision: R043; RoHS Status: ROHS_COMPLIANT; Rtd Power: N/A; Rtd Voltage: 7V; Status: Released; Texas Part Status: Under Review; Type: Diode; Vendor: TEXAS INSTRUMENTS; Vendor Part Number: TPD6E004RSER; Vendor Part Status: Active; Weight: 0.0033g
J4 = CONN_HEADER_2X10_P_V3: CONNECTOR, HEADER, FEMALE, RIGHT ANGLE, 2 ROW(S), 20 PIN(S), PITCH 2.54mm, PTH; ALT_SYMBOLS: SULLINS_SFH11PBPCD10RABK_A2A,SULLINS_SFH11PBPCD10RABK_A2C; Additional Datasheet URL: https://www.sullinscorp.com/product/?pn=SFH11-PBPC-D10-RA-BK&toggle=in; Budgetary Price: 0.78488 USD; Country of Origin: United States; Datasheet URL: https://s3.amazonaws.com/catalogspreads-pdf/PAGE123%20.100%20SFH11%20SERIES%20FEMALE%20HDR%20ST%20RA.pdf; Lead Time: 11; Mass: N/A; Maximum Operating Temperature: +105DEGC; Minimum Operating Temperature: -40DEGC; Mounting Type: PTH; NOTEfied URL: https://notefied-dynamic-precision.com/NOTEfiedWebInterface/part/show?partNumber=06-12237; Number of Positions: 20; Number of Rows: 2; Packing Size: N/A; Packing Type: Missing Info; Part Number: 06-12237; Part Type: Connector|HEADER|STANDARD; Pitch: 2.54mm; REACH/SVHC Compliance: Compliant; REACH/SVHC Details: SVHC List Version Jan 17, 2022 (223); REACH/SVHC Source: REACH Declaration; REACH/SVHC Status: Unaffected; ROHS: Compliant; Rated Current: 3A; Rated Voltage: N/A; Revision: R012; Status: Released; Texas Part Status: Under Review; Type: Connector; Vendor: SULLINS; Vendor Part Status: Active
P6 = CONN_HEADER_2X5: CONNECTOR, HEADER, MALE, STRAIGHT, 2 ROW(S), 10 PIN(S), PITCH 1.27mm, SMD; ALT_SYMBOLS: SAMTEC_FTSH10501FDVK_A2L,SAMTEC_FTSH10501FDVK_A2M,SAMTEC_FTSH10501FDVK_B2M,SAMTEC_FTSH10501FDVK_B2L; Additional Datasheet URL: https://www.samtec.com/products/ftsh-105-01-f-dv-k; AutoDoc File: http://notefied-dynamic-precision.com/DB/Apps/Desktop/Item/Object.aspx?id=50836; Budget Currency: USD; Budget Price: 1.700; Budgetary Price: 2.07959 USD; CLASS: IO; Country of Origin: China,Costa Rica,Malaysia,Singapore,Taiwan,United States,Vietnam; Datasheet URL: https://suddendocs.samtec.com/catalog_english/ftsh_smt.pdf; Datasheet URL 1: http://www.samtec.com/documents/webfiles/cpdf/FTSH-1XX-XX-XXX-DV-XXX-MKT.pdf; Datasheet URL 2: http://www.samtec.com/documents/webfiles/pdf/FTSH_SMT.PDF; FPLIST: SAMTEC_FTSH-105-01-F-DV-K-10N,SAMTEC_FTSH-105-01-F-DV-K-10L,SAMTEC_FTSH-105-01-F-DV-K-10M; Lead Time: 14; LifeCycle Status: MATURITY; MPN Status: ACTIVE; Manufacturer: SAMTEC; Mass: 0.31700g; Max Oper Temp: +125DEGC; Maximum Operating Temperature: +125DEGC; Min Oper Temp: -55DEGC; Minimum Operating Temperature: -55DEGC; Mounting Type: SMD; NOTE Status: PREFERRED; NOTEfied URL: https://notefied-dynamic-precision.com/NOTEfiedWebInterface/part/show?partNumber=06-00166; No Of Pos: 10; No Of Rows: 2; Number of Positions: 10; Number of Rows: 2; Old Footprint: SAMTEC_FTSH-105-01-F-DV-K-10N,CONN_MALE_2X5; Packing Size: 92; Packing Type: Tube; Part Number: 06-00166; Part Type: Connector|HEADER|STANDARD; Pitch: 1.27mm; REACH/SVHC Compliance: Compliant; REACH/SVHC Details: SVHC List Version Jun 10, 2022 (224); REACH/SVHC Source: REACH Declaration & Material Declaration; REACH/SVHC Status: Unaffected; ROHS: Compliant; Rated Current: 3.4A; Revision: R048; RoHS Status: ROHS_COMPLIANT; Rtd Current: 1.75A; Status: Released; Texas Part Status: Under Review; Type: Connector; Vendor: SAMTEC; Vendor Part Status: Active; WEIGHT: 0.65614g
U4 = IC_EEPROM_CAT24C08_TSOT23-5: IC, MEMORY, EEPROM, SERIAL, I2C, 8kbit, 1k X 8bit, 900ns, 1.7V TO 5.5V, TSOT23-5, SMD; ALT_SYMBOLS: SOT95P280X100-5A2L,SOT95P280X100-5A2M; Additional Datasheet URL: https://www.onsemi.com/products/timing-logic-memory/memory/eeprom-memory/cat24c08; Budgetary Price: 0.1867 USD; Country of Origin: Thailand; Datasheet URL: https://www.onsemi.com/download/data-sheet/pdf/cat24c01-d.pdf; Lead Time: 23; Mass: 0.01268g; Maximum Operating Temperature: +85DEGC; Minimum Operating Temperature: -40DEGC; Mounting Type: SMD; NOTEfied URL: https://notefied-dynamic-precision.com/NOTEfiedWebInterface/part/show?partNumber=18-36044; PCB Package: TSOT23-5; Packing Size: 3000; Packing Type: Tape & Reel; Part Number: 18-36044; Part Type: IC|MEMORY|ROM|EEPROM|SERIAL|I2C; REACH/SVHC Compliance: Compliant; REACH/SVHC Details: SVHC List Version Jan 16, 2020 (205); REACH/SVHC Source: REACH Declaration; REACH/SVHC Status: Unaffected; ROHS: Compliant; Rated Voltage: 1.7V TO 5.5V; Revision: R024; Status: Released; Texas Part Status: Under Review; Type: IC; Vendor: ONSEMI; Vendor Part Number: CAT24C08TDI-GT3; Vendor Part Status: Active

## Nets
5V0_BP: J1.2 J4.18 P2.1 U4.4(VCC)
GND: C55.2 CR2.4(GND) CR3.4(GND) CR4.1(C) CR5.1(C) J1.4 J2.2 J4.1 J4.7 J4.13 J4.19 J4.20 P2.2 P2.3 P3.2 P3.3 P4.2 P4.3 P4.4 P4.5 P4.6 P6.3 P6.5 P6.9 SW1.1 SW1.2 SW1.3 SW2.1 SW2.2 SW2.4 U3.4(GND) U3.9(EGP) U4.2(VSS) U4.5(WP) ; also on sheet 1 4
BP_RESET: J2.11 R8.1 R9.1
DIO3: P4.1 R16.1 U1.12(DIO_3)
DIO3_RF_PA: R16.2 ; also on sheet 1
DIO4_SCL: J1.17 R3.1 U1.13(DIO_4)
DIO5_SDA: J1.19 R2.1 U1.14(DIO_5)
DIO6_RLED: P1.2 U1.15(DIO_6)
DIO7_GLED: P1.4 U1.16(DIO_7)
DIO8_MISO: J2.14 U1.18(DIO_8)
DIO9_MOSI: J2.12 U1.19(DIO_9)
DIO10_SCLK: J1.13 U1.20(DIO_10)
DIO11: J2.6 U1.21(DIO_11)
DIO14_BTN2: J2.8 R13.2 U1.28(DIO_14)
DIO15_BTN1: J2.20 R12.2 U1.29(DIO_15)
DIO16_TDO: CR2.5(IO4) J4.4 P6.6 R6.2 U1.34(DIO_16)
DIO17_TDI: CR2.3(IO3) J4.2 P6.8 R7.2 U1.35(DIO_17)
DIO19: J2.4 U1.37(DIO_19)
DIO20: J2.5 U1.38(DIO_20)
DIO21: J1.15 U1.39(DIO_21)
DIO22: J1.9 U1.40(DIO_22)
DIO23_Analog: J1.3 U1.50(DIO_23)
DIO24_Analog: J1.11 U1.51(DIO_24)
DIO25_Analog: J1.6 U1.52(DIO_25)
DIO26_Analog: J1.8 U1.53(DIO_26)
DIO27_Analog: J1.10 U1.54(DIO_27)
DIO28_Analog: J1.12 U1.55(DIO_28)
DIO29_Analog: J1.14 U1.56(DIO_29)
DIO30_Analog: J1.16 U1.57(DIO_30)
DIO34: P5.1 R17.2 U1.10(DIO_34)
DIO34_RF_2G4: R17.1 ; also on sheet 1
DIO35: P5.2 R18.2 U1.11(DIO_35)
DIO35_RF_SUB1G: R18.1 ; also on sheet 1
DIO36_Flash_MOSI: P5.3 U1.22(DIO_36) U3.5(SI/SIO0)
DIO37_Flash_MISO: P5.4 U1.23(DIO_37) U3.2(SO/SIO1)
DIO38_Flash_CS: P5.5 R24.1 U1.24(DIO_38) U3.1(nCS)
DIO39_Flash_SCLK: P5.6 U1.25(DIO_39) U3.6(SCLK)
DIO40: R8.2 R10.2 U1.41(DIO_40)
DIO41: J2.18 U1.42(DIO_41)
DIO42: J2.16 U1.43(DIO_42)
DIO43: J1.18 U1.44(DIO_43)
DIO44: J1.20 U1.45(DIO_44)
DIO45: J2.7 R19.1 U1.46(DIO_45)
DIO46: J2.3 R20.1 U1.58(DIO_46)
DIO47: J2.1 R21.1 U1.59(DIO_47)
LP_RESET: J2.10 R10.1 R11.1
WMCU_RESET: CR2.2(IO2) J4.10 P6.10 R9.2 R11.2 ; also on sheet 1
WMCU_RXD: J1.5 J4.14 U1.26(DIO_12)
WMCU_SWO: CR3.5(IO4) J2.9 J4.11 U1.36(DIO_18)
WMCU_TCK: CR2.6(IO5) J4.6 P6.4 R5.2 ; also on sheet 1
WMCU_TMS: CR2.7(IO6) J4.8 P6.2 R4.2 ; also on sheet 1
WMCU_TXD: J1.7 J4.12 U1.27(DIO_13)
WMCU_VDD: CR2.8(VCC) CR3.8(VCC) J1.1 J4.16 P3.1 P6.1 R2.2 R3.2 R22.2 R23.2 R24.2 R25.2 ; also on sheet 1
XDS_BoardID_SCL: J4.15 U4.1(SCL)
XDS_BoardID_SDA: J4.17 U4.3(SDA)
XDS_GPIO1: CR3.1(IO1) J4.3 R19.2
XDS_GPIO2: CR3.2(IO2) J4.5 R20.2
XDS_GPIO3: CR3.3(IO3) J4.9 R21.2
N3109894: J2.13 R4.1
N3109960: J2.15 R5.1
N3110034: J2.17 R6.1
N3110086: J2.19 R7.1
N3110356: P1.1 R15.2
N3110380: P1.3 R14.2
N3110768: R12.1 SW1.4
N3110772: R13.1 SW2.3
N3110876: CR4.2(A) R14.1
N3110880: CR5.2(A) R15.1
N3111246: C55.1 R25.1 U3.8(VCC)
N3111262: R22.1 U3.7(nRST/SIO3)
N3111266: R23.1 U3.3(nWP/SIO2)

Not connected (* = marked no-connect by the designer): CR2 1(IO1)*; CR3 6(IO5)* 7(IO6)*; P6 7*

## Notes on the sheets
sheet 2
- BoosterPack Headers and Peripherals
- 1
- 2
- 21
- 22
- 39
- 40
- 19
- 20
- 3
- 23
- 38
- 18
- 4
- 24
- 37
- 17
- 5
- 25
- 36
- 16
- 6
- 26
- 35
- 15
- 7
- 8
- 27
- 28
- 33
- 34
- 13
- 14
- 9
- 29
- 32
- 12
- 10
- 30
- 31
- 11
- Wireless MCU IO block
- Buttons / LEDs
- External flash
- Extra headers
sheet 3
- XDS110 Debugger Interface
- DEBUG
- Board ID
- Use P5 for debugging
  the wireless MCU with an
  external debugger
  (requires that all
  jumpers be removed)
